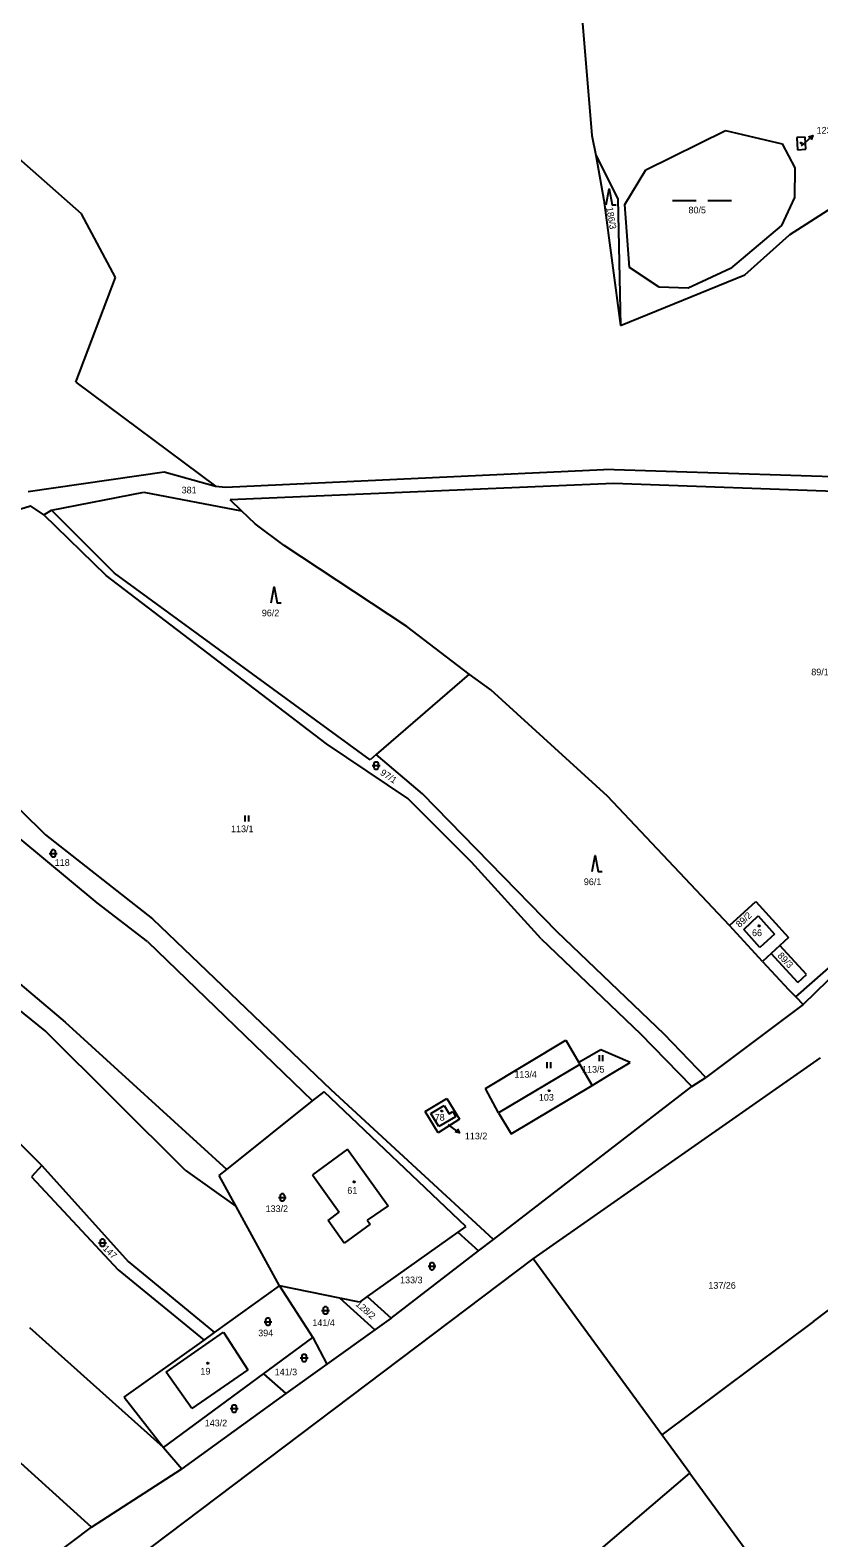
# Model space of a CAD drawing. Extents: x -811039 to -805820, y -1161436 to -1155864.
# Drawn here: x -806971.7 to -806771.7, y -1158370.8 to -1157988.2 of the extents above; entities that cross this region are included whole.
import ezdxf

# ---------------------------------------------------------------- set-up
doc = ezdxf.new("R2010")
doc.units = 0
for name, color, linetype in [('Default', 7, 'Continuous'), ('KN_HRANICE', 7, 'Continuous'), ('KN_KULTURY', 7, 'Continuous'), ('KN_PARCELY', 7, 'Continuous')]:
    doc.layers.add(name, color=color, linetype=linetype)

# ---------------------------------------------------------------- blocks, each defined once
blk = doc.blocks.new('306')
at = {"layer": 'Default'}
for p, q in [((-0.5, 1.5), (-0.5, 0)), ((0.5, 0), (0.5, 1.5))]:
    blk.add_line(p, q, dxfattribs=at)
blk = doc.blocks.new('308')
at = {"layer": 'Default'}
blk.add_lwpolyline([(-0.75, 0), (0, 4), (0.75, 0), (1.75, 0)], dxfattribs=at)
blk = doc.blocks.new('316')
at = {"layer": 'Default'}
for points in [[(-1, 1), (0.27, 1), (1, 1)], [(-0.5, 1.5), (-0.4, 1.79), (-0.15, 1.97), (0.16, 1.97), (0.41, 1.79), (0.51, 1.5), (0.51, 0.5), (0.41, 0.21), (0.16, 0.03), (-0.15, 0.03), (-0.4, 0.21), (-0.5, 0.5), (-0.5, 1.5)]]:
    blk.add_lwpolyline(points, dxfattribs=at)
blk = doc.blocks.new('803')
at = {"layer": 'Default'}
for p, q in [((-7.5, 0), (-1.5, 0)), ((1.5, 0), (7.5, 0))]:
    blk.add_line(p, q, dxfattribs=at)
blk = doc.blocks.new('10292')
at = {"layer": 'Default'}
blk.add_line((0, 3), (0, 0), dxfattribs=at)
blk.add_lwpolyline([(-0.5, 2), (0, 3), (0.5, 2)], dxfattribs=at)
blk = doc.blocks.new('402')
at = {"layer": 'Default'}
blk.add_lwpolyline([(0.09, 0.15), (0.18, 0), (0.09, -0.15), (-0.09, -0.15), (-0.18, 0), (-0.09, 0.15), (0.09, 0.15)], dxfattribs=at)

msp = doc.modelspace()

# ---------------------------------------------------------------- linework, layer by layer
at = {"layer": 'KN_HRANICE'}
for p, q in [((-806831.65, -1157986.44), (-806829.24, -1158014.95)), ((-806829.24, -1158014.95), (-806828.28, -1158019.94)), ((-806815.6, -1158023.66), (-806795.32, -1158013.71)), ((-806795.32, -1158013.71), (-806780.95, -1158017.13)), ((-806775.18, -1158015.36), (-806777.27, -1158015.52)), ((-806777.27, -1158015.52), (-806777.06, -1158018.61)), ((-806774.99, -1158018.42), (-806775.18, -1158015.36)), ((-806958.71, -1158034.89), (-806978.9, -1158017.04)), ((-806828.28, -1158019.94), (-806826.26, -1158031.41)), ((-806828.28, -1158019.94), (-806822.69, -1158031.03)), ((-806780.95, -1158017.13), (-806777.75, -1158023.16)), ((-806777.06, -1158018.61), (-806774.99, -1158018.42)), ((-806820.89, -1158032.46), (-806815.6, -1158023.66)), ((-806777.75, -1158023.16), (-806777.87, -1158030.68)), ((-806756.36, -1158025.64), (-806779.2, -1158040.26)), ((-806826.26, -1158031.41), (-806822.02, -1158063.21)), ((-806822.69, -1158031.03), (-806822.02, -1158063.21)), ((-806777.87, -1158030.68), (-806781.15, -1158037.79)), ((-806950.1, -1158050.97), (-806958.71, -1158034.89)), ((-806819.72, -1158048.5), (-806820.89, -1158032.46)), ((-806781.15, -1158037.79), (-806794.11, -1158048.73)), ((-806790.45, -1158050.34), (-806779.2, -1158040.26)), ((-806822.02, -1158063.21), (-806790.45, -1158050.34)), ((-806812.15, -1158053.5), (-806819.72, -1158048.5)), ((-806794.11, -1158048.73), (-806804.86, -1158053.74)), ((-806960.13, -1158077.6), (-806950.1, -1158050.97)), ((-806804.86, -1158053.74), (-806812.15, -1158053.5)), ((-806960.13, -1158077.6), (-806924.76, -1158103.98)), ((-806972.21, -1158105.33), (-806937.74, -1158100.34)), ((-806937.74, -1158100.34), (-806924.76, -1158103.98)), ((-806922.15, -1158104.21), (-806826.2, -1158099.73)), ((-806755.75, -1158102.03), (-806826.2, -1158099.73)), ((-806924.76, -1158103.98), (-806922.15, -1158104.21)), ((-806823.76, -1158103.31), (-806921.01, -1158107.38)), ((-806754.99, -1158105.78), (-806823.76, -1158103.31)), ((-806966.3, -1158110.08), (-806942.91, -1158105.49)), ((-806942.91, -1158105.49), (-806918.14, -1158110.23)), ((-806918.14, -1158110.23), (-806921.01, -1158107.38)), ((-806980.48, -1158111.68), (-806971.65, -1158108.95)), ((-806968.24, -1158111.24), (-806971.65, -1158108.95)), ((-806968.24, -1158111.24), (-806966.3, -1158110.08)), ((-806952.42, -1158126.65), (-806968.24, -1158111.24)), ((-806966.3, -1158110.08), (-806950.37, -1158126.05)), ((-806914.62, -1158113.48), (-806918.14, -1158110.23)), ((-806907.27, -1158119.01), (-806914.62, -1158113.48)), ((-806876.2, -1158139.53), (-806907.27, -1158119.01)), ((-806896.6, -1158169.34), (-806952.42, -1158126.65)), ((-806885.53, -1158173.39), (-806950.37, -1158126.05)), ((-806860.39, -1158151.65), (-806876.2, -1158139.53)), ((-806860.39, -1158151.65), (-806883.96, -1158172.03)), ((-806854.9, -1158155.63), (-806860.39, -1158151.65)), ((-806825.32, -1158182.62), (-806854.9, -1158155.63)), ((-806875.95, -1158183.18), (-806896.6, -1158169.34)), ((-806883.96, -1158172.03), (-806885.53, -1158173.39)), ((-806872.23, -1158182), (-806883.96, -1158172.03)), ((-806986.84, -1158173.73), (-806967.86, -1158192.42)), ((-806859.82, -1158199.37), (-806875.95, -1158183.18)), ((-806838.09, -1158217.06), (-806872.23, -1158182)), ((-806794.32, -1158215.46), (-806825.32, -1158182.62)), ((-806954.76, -1158209.69), (-806974.74, -1158193.03)), ((-806967.86, -1158192.42), (-806940.68, -1158213.7)), ((-806842.13, -1158218.84), (-806859.82, -1158199.37)), ((-806775.62, -1158235.5), (-806740.96, -1158201.43)), ((-806941.94, -1158219.49), (-806954.76, -1158209.69)), ((-806794.32, -1158215.46), (-806787.67, -1158209.35)), ((-806787.67, -1158209.35), (-806779.38, -1158218.47)), ((-806992.99, -1158214.58), (-806962.84, -1158239.91)), ((-806940.68, -1158213.7), (-806895.39, -1158257.1)), ((-806790.74, -1158216.43), (-806787.11, -1158212.99)), ((-806787.11, -1158212.99), (-806782.89, -1158217.6)), ((-806842.13, -1158218.84), (-806816.89, -1158242.94)), ((-806810.96, -1158243.02), (-806838.09, -1158217.06)), ((-806786.01, -1158224.54), (-806794.32, -1158215.46)), ((-806786.64, -1158220.97), (-806790.74, -1158216.43)), ((-806782.89, -1158217.6), (-806786.64, -1158220.97)), ((-806779.38, -1158218.47), (-806781.59, -1158220.49)), ((-806777.52, -1158233.56), (-806758.12, -1158216.37)), ((-806941.94, -1158219.49), (-806900.08, -1158259.94)), ((-806783.8, -1158222.51), (-806786.01, -1158224.54)), ((-806781.59, -1158220.49), (-806783.8, -1158222.51)), ((-806777.04, -1158229.89), (-806783.8, -1158222.51)), ((-806774.82, -1158227.88), (-806781.59, -1158220.49)), ((-806967.9, -1158242.14), (-806991.49, -1158223.13)), ((-806786.01, -1158224.54), (-806779.35, -1158231.7)), ((-806777.04, -1158229.89), (-806774.82, -1158227.88)), ((-806779.35, -1158231.7), (-806777.52, -1158233.56)), ((-806777.52, -1158233.56), (-806775.62, -1158235.5)), ((-806775.62, -1158235.5), (-806800.39, -1158254.02)), ((-806962.84, -1158239.91), (-806921.81, -1158277.3)), ((-806932.39, -1158277.49), (-806967.9, -1158242.14)), ((-806856.25, -1158256.75), (-806835.87, -1158244.53)), ((-806835.87, -1158244.53), (-806832.6, -1158250.2)), ((-806803.92, -1158256.3), (-806816.89, -1158242.94)), ((-806800.39, -1158254.02), (-806810.96, -1158243.02)), ((-806844.14, -1158300.03), (-806771.28, -1158248.97)), ((-806826.98, -1158246.94), (-806832.6, -1158250.2)), ((-806819.58, -1158250.22), (-806826.98, -1158246.94)), ((-806832.33, -1158250.66), (-806840.86, -1158255.74)), ((-806832.6, -1158250.2), (-806832.33, -1158250.66)), ((-806832.33, -1158250.66), (-806829.16, -1158256.01)), ((-806829.16, -1158256.01), (-806824.76, -1158253.35)), ((-806824.76, -1158253.35), (-806819.58, -1158250.22)), ((-806854.22, -1158295.07), (-806895.39, -1158257.1)), ((-806852.92, -1158262.92), (-806856.25, -1158256.75)), ((-806854.22, -1158295.07), (-806803.92, -1158256.3)), ((-806849.74, -1158268.26), (-806829.16, -1158256.01)), ((-806840.86, -1158255.74), (-806844, -1158257.61)), ((-806803.92, -1158256.3), (-806800.39, -1158254.02)), ((-806987.01, -1158258.28), (-806968.76, -1158276.34)), ((-806921.81, -1158277.3), (-806900.08, -1158259.94)), ((-806900.08, -1158259.94), (-806897.13, -1158257.59)), ((-806861.24, -1158291.79), (-806897.13, -1158257.59)), ((-806871.53, -1158262.63), (-806866.02, -1158259.28)), ((-806866.02, -1158259.28), (-806862.83, -1158264.59)), ((-806844, -1158257.61), (-806852.92, -1158262.92)), ((-806868.25, -1158268), (-806871.53, -1158262.63)), ((-806870.09, -1158263.14), (-806866.72, -1158261.12)), ((-806868.11, -1158266.45), (-806870.09, -1158263.14)), ((-806862.83, -1158264.59), (-806868.25, -1158268)), ((-806863.83, -1158263.95), (-806868.11, -1158266.45)), ((-806866.72, -1158261.12), (-806865.49, -1158263.19)), ((-806865.49, -1158263.19), (-806864.56, -1158262.65)), ((-806864.56, -1158262.65), (-806863.83, -1158263.95)), ((-806852.92, -1158262.92), (-806849.74, -1158268.26)), ((-806891.22, -1158272.18), (-806900.16, -1158278.66)), ((-806891.22, -1158272.18), (-806880.89, -1158286.52)), ((-806968.76, -1158276.34), (-806971.42, -1158279.21)), ((-806971.42, -1158279.21), (-806949.38, -1158302.82)), ((-806968.76, -1158276.34), (-806946.85, -1158300.67)), ((-806932.39, -1158277.49), (-806919.47, -1158286.75)), ((-806923.78, -1158278.88), (-806921.81, -1158277.3)), ((-806919.47, -1158286.75), (-806923.78, -1158278.88)), ((-806900.16, -1158278.66), (-806893.37, -1158288.16)), ((-806908.45, -1158306.85), (-806919.47, -1158286.75)), ((-806880.89, -1158286.52), (-806886.22, -1158290.18)), ((-806896.13, -1158290.31), (-806893.37, -1158288.16)), ((-806892.12, -1158296.04), (-806896.13, -1158290.31)), ((-806885.47, -1158291.24), (-806892.12, -1158296.04)), ((-806886.22, -1158290.18), (-806885.47, -1158291.24)), ((-806863.26, -1158293.22), (-806886.25, -1158309.58)), ((-806861.24, -1158291.79), (-806863.26, -1158293.22)), ((-806863.26, -1158293.22), (-806858.02, -1158298)), ((-806858.02, -1158298), (-806854.22, -1158295.07)), ((-806880.19, -1158315.08), (-806858.02, -1158298)), ((-806963.69, -1158390.26), (-806844.14, -1158300.03)), ((-806949.38, -1158302.82), (-806927.61, -1158320.6)), ((-806946.85, -1158300.67), (-806924.98, -1158318.71)), ((-806836.79, -1158310.08), (-806844.14, -1158300.03)), ((-806924.98, -1158318.71), (-806908.45, -1158306.85)), ((-806908.45, -1158306.85), (-806900.07, -1158319.96)), ((-806893.15, -1158309.97), (-806908.45, -1158306.85)), ((-806773.03, -1158315.88), (-806759.33, -1158305.54)), ((-806888.21, -1158310.98), (-806893.15, -1158309.97)), ((-806884.28, -1158318.02), (-806893.15, -1158309.97)), ((-806886.25, -1158309.58), (-806888.21, -1158310.98)), ((-806886.25, -1158309.58), (-806880.19, -1158315.08)), ((-806811.5, -1158344.69), (-806836.79, -1158310.08)), ((-806956.16, -1158368.04), (-807012.37, -1158317.33)), ((-806937.93, -1158347.83), (-806971.82, -1158317.52)), ((-806884.28, -1158318.02), (-806896.46, -1158326.7)), ((-806880.19, -1158315.08), (-806884.28, -1158318.02)), ((-806773.03, -1158315.88), (-806811.5, -1158344.69)), ((-806947.86, -1158335.13), (-806927.61, -1158320.6)), ((-806937.26, -1158328.73), (-806922.67, -1158318.61)), ((-806927.61, -1158320.6), (-806924.98, -1158318.71)), ((-806922.67, -1158318.61), (-806916.52, -1158328.12)), ((-806912.58, -1158329.17), (-806900.07, -1158319.96)), ((-806900.07, -1158319.96), (-806896.46, -1158326.7)), ((-806937.93, -1158347.83), (-806912.58, -1158329.17)), ((-806930.76, -1158337.94), (-806937.26, -1158328.73)), ((-806916.52, -1158328.12), (-806930.76, -1158337.94)), ((-806912.58, -1158329.17), (-806906.86, -1158334.2)), ((-806896.46, -1158326.7), (-806906.86, -1158334.2)), ((-806947.86, -1158335.13), (-806937.93, -1158347.83)), ((-806906.86, -1158334.2), (-806933.28, -1158353.24)), ((-806804.42, -1158354.37), (-806811.5, -1158344.69)), ((-806937.93, -1158347.83), (-806933.28, -1158353.24)), ((-806956.16, -1158368.04), (-806933.28, -1158353.24)), ((-806911.61, -1158445.88), (-806804.42, -1158354.37)), ((-806804.42, -1158354.37), (-806771.88, -1158398.73)), ((-806972.28, -1158380.19), (-806956.16, -1158368.04))]:
    msp.add_line(p, q, dxfattribs=at)
at = {"layer": 'KN_PARCELY'}
for p, q in [((-806776.09, -1158017.63), (-806775.42, -1158017.02)), ((-806865.72, -1158265.93), (-806865.29, -1158266.24))]:
    msp.add_line(p, q, dxfattribs=at)

# ---------------------------------------------------------------- block references
at = {"layer": 'KN_KULTURY'}
for name, p in [('402', (-806776.19, -1158016.89)), ('308', (-806824.84, -1158032.53)), ('803', (-806801.3, -1158031.51)), ('308', (-806909.85, -1158133.53)), ('316', (-806883.99, -1158175.85)), ('306', (-806916.76, -1158189.05)), ('316', (-806965.88, -1158198.14)), ('308', (-806828.4, -1158201.68)), ('402', (-806786.81, -1158215.5)), ('306', (-806826.94, -1158249.83)), ('306', (-806840.15, -1158251.62)), ('402', (-806840.09, -1158257.34)), ('402', (-806867.35, -1158262.48)), ('316', (-806907.76, -1158285.42)), ('402', (-806889.53, -1158280.45)), ('316', (-806953.4, -1158296.93)), ('316', (-806869.81, -1158302.86)), ('316', (-806896.84, -1158314.1)), ('316', (-806911.42, -1158316.95)), ('316', (-806902.25, -1158326.13)), ('402', (-806926.64, -1158326.47)), ('316', (-806920.01, -1158338.99))]:
    msp.add_blockref(name, p, dxfattribs=at)
at = {"layer": 'KN_PARCELY'}
for p, rotation in [((-806775.42, -1158017.02), -47.73800199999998), ((-806865.29, -1158266.24), -125.54567000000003)]:
    msp.add_blockref('10292', p, dxfattribs=dict(at, rotation=rotation))

# ---------------------------------------------------------------- texts
for s, height, p in [('123', 1.7, (-806772.25, -1158014.5)), ('123', 0.1, (-806776.07, -1158017.63)), ('80/5', 1.7, (-806804.75, -1158034.73)), ('381', 1.7, (-806933.31, -1158105.79)), ('96/2', 1.7, (-806912.97, -1158136.97)), ('89/1', 1.7, (-806773.6, -1158151.94)), ('113/1', 1.7, (-806920.77, -1158191.75)), ('118', 1.7, (-806965.49, -1158200.29)), ('96/1', 1.7, (-806831.29, -1158205.18)), ('66', 1.7, (-806788.63, -1158218.12)), ('113/4', 1.7, (-806848.89, -1158254.04)), ('113/5', 1.7, (-806831.74, -1158252.76)), ('103', 1.7, (-806842.69, -1158259.86)), ('78', 1.7, (-806869.12, -1158264.94)), ('113/2', 0.1, (-806865.97, -1158265.93)), ('113/2', 1.7, (-806861.46, -1158269.68)), ('61', 1.7, (-806891.28, -1158283.5)), ('133/2', 1.7, (-806912.01, -1158288.12)), ('133/3', 1.7, (-806877.9, -1158306.2)), ('137/26', 1.7, (-806799.71, -1158307.59)), ('394', 1.7, (-806913.89, -1158319.65)), ('141/4', 1.7, (-806900.15, -1158317.06)), ('19', 1.7, (-806928.54, -1158329.36)), ('141/3', 1.7, (-806909.71, -1158329.55)), ('143/2', 1.7, (-806927.45, -1158342.5))]:
    msp.add_text(s, height=height, dxfattribs=at).set_placement(p)
for s, rotation, p in [('186/3', 279.661, (-806825.63, -1158033.27)), ('97/1', 325.898, (-806883.1, -1158177.02)), ('89/2', 42.456, (-806791.8, -1158216.06)), ('89/3', 313.064, (-806782.29, -1158223.19)), ('147', 316.044, (-806953.45, -1158297.55)), ('128/2', 318.163, (-806889.32, -1158311.69))]:
    msp.add_text(s, height=1.7, rotation=rotation, dxfattribs=at).set_placement(p)

doc.saveas('drawing.dxf')
